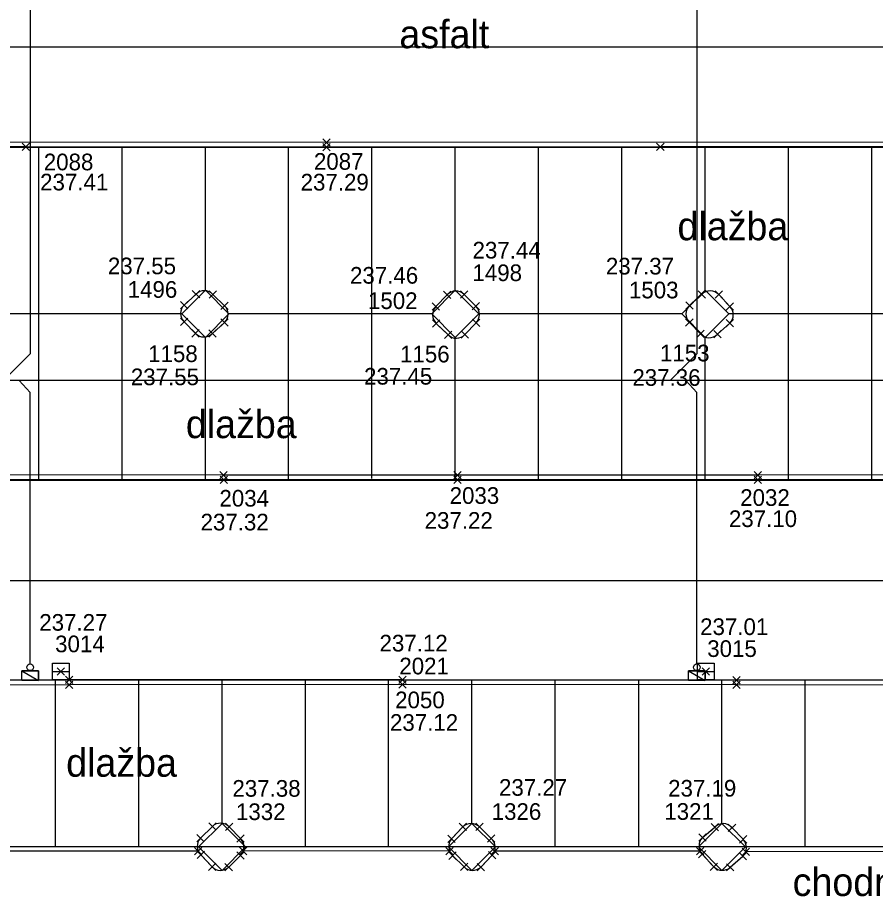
# Model space of a CAD drawing. Extents: x -264165 to -263733, y -1242319 to -1242245.
# Drawn here: x -263851.2 to -263825.46, y -1242299.47 to -1242273.09 of the extents above; entities that cross this region are included whole.
import ezdxf

# ---------------------------------------------------------------- set-up
doc = ezdxf.new("R2010")
doc.units = 0
for name, color, linetype in [('KFA_BOD_CISLO', 7, 'Continuous'), ('KFA_BOD_SYMBOL', 7, 'Continuous'), ('KFA_BOD_VYSKA', 7, 'Continuous'), ('KFA_SO_20-2_OBRUBNIKY_DOLNA_HRANA', 7, 'Continuous'), ('KFA_SO_20-2_OBRUBNIKY_HORNA_HRANA', 7, 'Continuous'), ('KFA_UV_BOD_CISLO', 7, 'Continuous'), ('KFA_UV_BOD_SYMBOL', 7, 'Continuous'), ('KFA_UV_BOD_VYSKA', 7, 'Continuous'), ('POPIS', 7, 'Continuous'), ('PROJEKT_OBRUBNIKY_KOMUNIKACIE', 7, 'Continuous'), ('PROJEKT_TDZ_VODOROVNE', 7, 'Continuous'), ('SITUACIA_DSP_2D', 7, 'Continuous'), ('ULICNA_VPUST_POKLOP', 7, 'Continuous')]:
    doc.layers.add(name, color=color, linetype=linetype)

msp = doc.modelspace()

# ---------------------------------------------------------------- linework, layer by layer
at = {"layer": 'KFA_BOD_SYMBOL'}
for p, q in [((-263842.042, -1242276.948), (-263841.821, -1242276.728)), ((-263841.821, -1242276.948), (-263842.042, -1242276.728)), ((-263851.06, -1242277.086), (-263850.839, -1242276.866)), ((-263850.839, -1242277.086), (-263851.06, -1242276.866)), ((-263842.041, -1242277.09), (-263841.82, -1242276.869)), ((-263841.82, -1242277.09), (-263842.041, -1242276.869)), ((-263832.029, -1242277.086), (-263831.807, -1242276.866)), ((-263831.807, -1242277.086), (-263832.029, -1242276.866)), ((-263845.959, -1242281.505), (-263845.737, -1242281.284)), ((-263845.737, -1242281.505), (-263845.959, -1242281.284)), ((-263845.454, -1242281.512), (-263845.232, -1242281.292)), ((-263845.232, -1242281.512), (-263845.454, -1242281.292)), ((-263838.421, -1242281.525), (-263838.199, -1242281.303)), ((-263838.199, -1242281.525), (-263838.421, -1242281.303)), ((-263837.915, -1242281.512), (-263837.693, -1242281.291)), ((-263837.693, -1242281.512), (-263837.915, -1242281.291)), ((-263830.786, -1242281.512), (-263830.565, -1242281.292)), ((-263830.565, -1242281.512), (-263830.786, -1242281.292)), ((-263830.274, -1242281.518), (-263830.053, -1242281.296)), ((-263830.053, -1242281.518), (-263830.274, -1242281.296)), ((-263846.316, -1242281.83), (-263846.095, -1242281.61)), ((-263846.095, -1242281.83), (-263846.316, -1242281.61)), ((-263845.101, -1242281.853), (-263844.879, -1242281.633)), ((-263844.879, -1242281.853), (-263845.101, -1242281.633)), ((-263838.759, -1242281.877), (-263838.538, -1242281.656)), ((-263838.538, -1242281.877), (-263838.759, -1242281.656)), ((-263837.562, -1242281.867), (-263837.34, -1242281.647)), ((-263837.34, -1242281.867), (-263837.562, -1242281.647)), ((-263831.149, -1242281.843), (-263830.928, -1242281.623)), ((-263830.928, -1242281.843), (-263831.149, -1242281.623)), ((-263829.94, -1242281.874), (-263829.719, -1242281.654)), ((-263829.719, -1242281.874), (-263829.94, -1242281.654)), ((-263846.318, -1242282.335), (-263846.096, -1242282.113)), ((-263846.096, -1242282.335), (-263846.318, -1242282.113)), ((-263845.101, -1242282.35), (-263844.879, -1242282.129)), ((-263844.879, -1242282.35), (-263845.101, -1242282.129)), ((-263838.75, -1242282.38), (-263838.529, -1242282.16)), ((-263838.529, -1242282.38), (-263838.75, -1242282.16)), ((-263837.556, -1242282.366), (-263837.334, -1242282.144)), ((-263837.334, -1242282.366), (-263837.556, -1242282.144)), ((-263831.158, -1242282.35), (-263830.937, -1242282.129)), ((-263830.937, -1242282.35), (-263831.158, -1242282.129)), ((-263829.947, -1242282.374), (-263829.726, -1242282.154)), ((-263829.726, -1242282.374), (-263829.947, -1242282.154)), ((-263845.973, -1242282.68), (-263845.752, -1242282.458)), ((-263845.752, -1242282.68), (-263845.973, -1242282.458)), ((-263845.465, -1242282.683), (-263845.244, -1242282.461)), ((-263845.244, -1242282.683), (-263845.465, -1242282.461)), ((-263838.393, -1242282.722), (-263838.171, -1242282.502)), ((-263838.171, -1242282.722), (-263838.393, -1242282.502)), ((-263837.889, -1242282.717), (-263837.668, -1242282.495)), ((-263837.668, -1242282.717), (-263837.889, -1242282.495)), ((-263830.822, -1242282.694), (-263830.601, -1242282.474)), ((-263830.601, -1242282.694), (-263830.822, -1242282.474)), ((-263830.316, -1242282.708), (-263830.095, -1242282.487)), ((-263830.095, -1242282.708), (-263830.316, -1242282.487)), ((-263845.133, -1242286.937), (-263844.911, -1242286.715)), ((-263844.911, -1242286.937), (-263845.133, -1242286.715)), ((-263838.117, -1242286.931), (-263837.896, -1242286.711)), ((-263837.896, -1242286.931), (-263838.117, -1242286.711)), ((-263829.106, -1242286.933), (-263828.884, -1242286.711)), ((-263828.884, -1242286.933), (-263829.106, -1242286.711)), ((-263845.12, -1242287.078), (-263844.899, -1242286.856)), ((-263844.899, -1242287.078), (-263845.12, -1242286.856)), ((-263838.116, -1242287.076), (-263837.894, -1242286.855)), ((-263837.894, -1242287.076), (-263838.116, -1242286.855)), ((-263829.106, -1242287.073), (-263828.885, -1242286.852)), ((-263828.885, -1242287.073), (-263829.106, -1242286.852)), ((-263839.762, -1242293.073), (-263839.541, -1242292.853)), ((-263839.541, -1242293.073), (-263839.762, -1242292.853)), ((-263849.767, -1242293.228), (-263849.546, -1242293.007)), ((-263849.546, -1242293.228), (-263849.767, -1242293.007)), ((-263849.764, -1242293.08), (-263849.542, -1242292.86)), ((-263849.542, -1242293.08), (-263849.764, -1242292.86)), ((-263839.759, -1242293.218), (-263839.538, -1242292.997)), ((-263839.538, -1242293.218), (-263839.759, -1242292.997)), ((-263829.742, -1242293.083), (-263829.521, -1242292.863)), ((-263829.521, -1242293.083), (-263829.742, -1242292.863)), ((-263829.741, -1242293.231), (-263829.519, -1242293.011)), ((-263829.519, -1242293.231), (-263829.741, -1242293.011)), ((-263845.468, -1242297.478), (-263845.247, -1242297.258)), ((-263845.247, -1242297.478), (-263845.468, -1242297.258)), ((-263844.965, -1242297.492), (-263844.743, -1242297.272)), ((-263844.743, -1242297.492), (-263844.965, -1242297.272)), ((-263837.953, -1242297.492), (-263837.731, -1242297.271)), ((-263837.731, -1242297.492), (-263837.953, -1242297.271)), ((-263837.457, -1242297.492), (-263837.236, -1242297.271)), ((-263837.236, -1242297.492), (-263837.457, -1242297.271)), ((-263830.394, -1242297.497), (-263830.174, -1242297.275)), ((-263830.174, -1242297.497), (-263830.394, -1242297.275)), ((-263829.878, -1242297.518), (-263829.656, -1242297.296)), ((-263829.656, -1242297.518), (-263829.878, -1242297.296)), ((-263830.766, -1242297.813), (-263830.545, -1242297.593)), ((-263830.545, -1242297.813), (-263830.766, -1242297.593)), ((-263845.826, -1242297.832), (-263845.605, -1242297.61)), ((-263845.605, -1242297.832), (-263845.826, -1242297.61)), ((-263844.625, -1242297.84), (-263844.404, -1242297.62)), ((-263844.404, -1242297.84), (-263844.625, -1242297.62)), ((-263838.296, -1242297.847), (-263838.074, -1242297.627)), ((-263838.074, -1242297.847), (-263838.296, -1242297.627)), ((-263837.101, -1242297.843), (-263836.879, -1242297.622)), ((-263836.879, -1242297.843), (-263837.101, -1242297.622)), ((-263829.546, -1242297.865), (-263829.325, -1242297.644)), ((-263829.325, -1242297.865), (-263829.546, -1242297.644)), ((-263845.892, -1242298.217), (-263845.671, -1242297.995)), ((-263845.671, -1242298.217), (-263845.892, -1242297.995)), ((-263845.811, -1242298.33), (-263845.59, -1242298.11)), ((-263845.59, -1242298.33), (-263845.811, -1242298.11)), ((-263844.541, -1242298.215), (-263844.319, -1242297.994)), ((-263844.319, -1242298.215), (-263844.541, -1242297.994)), ((-263838.35, -1242298.221), (-263838.128, -1242297.999)), ((-263838.128, -1242298.221), (-263838.35, -1242297.999)), ((-263837.072, -1242298.343), (-263836.851, -1242298.123)), ((-263836.851, -1242298.343), (-263837.072, -1242298.123)), ((-263836.998, -1242298.221), (-263836.777, -1242298.001)), ((-263836.777, -1242298.221), (-263836.998, -1242298.001)), ((-263830.834, -1242298.224), (-263830.612, -1242298.002)), ((-263830.612, -1242298.224), (-263830.834, -1242298.002)), ((-263830.777, -1242298.312), (-263830.556, -1242298.09)), ((-263830.556, -1242298.312), (-263830.777, -1242298.09)), ((-263829.465, -1242298.241), (-263829.244, -1242298.019)), ((-263829.244, -1242298.241), (-263829.465, -1242298.019)), ((-263844.628, -1242298.35), (-263844.407, -1242298.129)), ((-263844.407, -1242298.35), (-263844.628, -1242298.129)), ((-263838.263, -1242298.355), (-263838.041, -1242298.133)), ((-263838.041, -1242298.355), (-263838.263, -1242298.133)), ((-263829.557, -1242298.37), (-263829.335, -1242298.15)), ((-263829.335, -1242298.37), (-263829.557, -1242298.15)), ((-263845.476, -1242298.688), (-263845.254, -1242298.468)), ((-263845.254, -1242298.688), (-263845.476, -1242298.468)), ((-263844.979, -1242298.701), (-263844.758, -1242298.48)), ((-263844.758, -1242298.701), (-263844.979, -1242298.48)), ((-263837.915, -1242298.694), (-263837.693, -1242298.474)), ((-263837.693, -1242298.694), (-263837.915, -1242298.474)), ((-263837.416, -1242298.7), (-263837.194, -1242298.478)), ((-263837.194, -1242298.7), (-263837.416, -1242298.478)), ((-263830.421, -1242298.69), (-263830.2, -1242298.468)), ((-263830.2, -1242298.69), (-263830.421, -1242298.468)), ((-263829.932, -1242298.705), (-263829.71, -1242298.485)), ((-263829.71, -1242298.705), (-263829.932, -1242298.485))]:
    msp.add_line(p, q, dxfattribs=at)
at = {"layer": 'KFA_SO_20-2_OBRUBNIKY_DOLNA_HRANA'}
for points in [[(-263816.727, -1242276.824), (-263824.896, -1242276.832), (-263841.932, -1242276.838), (-263860.969, -1242276.825), (-263872.991, -1242276.822), (-263881, -1242276.818), (-263897.019, -1242276.831), (-263905.035, -1242276.846), (-263913.057, -1242276.848), (-263917.557, -1242276.899)], [(-263817.074, -1242276.98), (-263824.904, -1242276.976), (-263831.918, -1242276.976), (-263841.931, -1242276.979), (-263850.949, -1242276.976), (-263860.958, -1242276.969), (-263872.991, -1242276.965), (-263880.996, -1242276.964), (-263889.006, -1242276.968), (-263897.017, -1242276.976), (-263905.035, -1242276.99), (-263913.048, -1242276.994), (-263917.092, -1242277.009)], [(-263819.103, -1242286.786), (-263819.439, -1242286.959), (-263828.996, -1242286.962), (-263838.005, -1242286.965), (-263845.009, -1242286.967), (-263853.017, -1242286.968), (-263861.032, -1242286.966), (-263868.037, -1242286.96), (-263877.037, -1242286.952), (-263886.053, -1242286.951), (-263895.068, -1242286.953), (-263904.067, -1242286.955), (-263910.084, -1242286.961), (-263917.346, -1242286.958)], [(-263819.419, -1242286.819), (-263828.995, -1242286.822), (-263838.007, -1242286.821), (-263845.022, -1242286.826), (-263853.012, -1242286.818), (-263861.03, -1242286.825), (-263868.034, -1242286.816), (-263877.043, -1242286.812), (-263886.05, -1242286.81), (-263895.064, -1242286.807), (-263904.07, -1242286.816), (-263910.08, -1242286.821), (-263917.062, -1242286.824)], [(-263817.492, -1242292.982), (-263829.632, -1242292.973), (-263839.651, -1242292.963), (-263849.653, -1242292.97), (-263858.67, -1242292.978), (-263866.671, -1242292.969), (-263877.683, -1242292.971), (-263887.693, -1242292.984), (-263898.705, -1242293.002), (-263909.705, -1242293.003), (-263917.41, -1242292.997)], [(-263817.431, -1242293.129), (-263829.63, -1242293.121), (-263839.649, -1242293.107), (-263849.656, -1242293.117), (-263858.667, -1242293.124), (-263866.668, -1242293.115), (-263877.682, -1242293.116), (-263887.695, -1242293.128), (-263898.705, -1242293.142), (-263909.706, -1242293.151), (-263917.057, -1242293.143)]]:
    msp.add_lwpolyline(points, dxfattribs=at)
at = {"layer": 'KFA_SO_20-2_OBRUBNIKY_HORNA_HRANA'}
for p, q in [((-263845.848, -1242281.394), (-263846.205, -1242281.72)), ((-263844.99, -1242281.743), (-263845.343, -1242281.402)), ((-263838.31, -1242281.414), (-263838.649, -1242281.766)), ((-263837.451, -1242281.757), (-263837.804, -1242281.401)), ((-263830.676, -1242281.402), (-263831.039, -1242281.733)), ((-263829.829, -1242281.764), (-263830.164, -1242281.407)), ((-263846.207, -1242282.224), (-263845.862, -1242282.569)), ((-263845.355, -1242282.572), (-263844.99, -1242282.239)), ((-263838.639, -1242282.27), (-263838.282, -1242282.612)), ((-263837.779, -1242282.606), (-263837.445, -1242282.255)), ((-263830.711, -1242282.584), (-263831.047, -1242282.239)), ((-263830.205, -1242282.597), (-263829.836, -1242282.264)), ((-263845.715, -1242297.721), (-263845.357, -1242297.368)), ((-263844.854, -1242297.382), (-263844.514, -1242297.73)), ((-263837.842, -1242297.381), (-263838.185, -1242297.737)), ((-263837.346, -1242297.381), (-263836.99, -1242297.732)), ((-263830.655, -1242297.703), (-263830.284, -1242297.386)), ((-263829.767, -1242297.407), (-263829.436, -1242297.754)), ((-263845.781, -1242298.106), (-263851.901, -1242298.107)), ((-263838.239, -1242298.11), (-263844.43, -1242298.104)), ((-263830.723, -1242298.113), (-263836.888, -1242298.111)), ((-263823.183, -1242298.117), (-263829.355, -1242298.13)), ((-263845.365, -1242298.578), (-263845.7, -1242298.22)), ((-263844.518, -1242298.239), (-263844.868, -1242298.59)), ((-263837.804, -1242298.584), (-263838.152, -1242298.244)), ((-263836.961, -1242298.233), (-263837.305, -1242298.589)), ((-263830.311, -1242298.579), (-263830.666, -1242298.201)), ((-263829.821, -1242298.595), (-263829.446, -1242298.26))]:
    msp.add_line(p, q, dxfattribs=at)
for centre, major_axis, ratio, start_param, end_param in [((-263845.599, -1242281.636), (-0.343, 0.056), 0.999175, 4.045169, 5.673101), ((-263838.051, -1242281.645), (-0.126, -0.323), 0.999722, 2.721671, 4.357418), ((-263830.422, -1242281.651), (-0.309, -0.176), 0.999729, 3.379744, 4.99023), ((-263845.953, -1242281.973), (-0.018, -0.356), 0.999068, 3.974465, 5.542291), ((-263845.226, -1242281.991), (0.06, 0.337), 0.999412, 4.079854, 5.699677), ((-263838.401, -1242282.013), (-0.079, -0.341), 0.999704, 4.155248, 5.763516), ((-263837.699, -1242282.009), (-0.144, 0.323), 0.99968, 3.523747, 5.0845), ((-263830.804, -1242281.99), (-0.022, -0.347), 0.999146, 3.9461, 5.574386), ((-263830.083, -1242282.01), (-0.272, 0.227), 0.99997, 3.037553, 4.607722), ((-263845.607, -1242282.326), (0.351, -0.032), 0.998916, 3.994193, 5.600253), ((-263838.033, -1242282.364), (0.351, -0.012), 0.999101, 3.961069, 5.557532), ((-263830.452, -1242282.351), (0.321, 0.135), 0.999067, 3.476005, 5.100322), ((-263845.113, -1242297.625), (-0.327, -0.14), 0.997484, 3.491315, 5.065966), ((-263837.594, -1242297.626), (-0.297, -0.182), 0.999524, 3.371532, 4.952837), ((-263830.035, -1242297.634), (-0.35, 0.031), 0.999187, 3.933605, 5.587069), ((-263845.458, -1242297.963), (-0.098, -0.34), 0.997413, 4.239538, 5.808156), ((-263844.763, -1242297.982), (-0.038, 0.353), 0.998712, 3.796865, 5.39506), ((-263837.883, -1242297.972), (0.034, -0.382), 0.99692, 3.962445, 5.412131), ((-263837.217, -1242297.997), (0.045, 0.346), 0.998564, 4.096141, 5.7027), ((-263830.39, -1242297.958), (-0.074, 0.36), 0.998996, 0.600277, 2.089271), ((-263829.677, -1242298.002), (0.143, 0.315), 0.999689, 4.2992, 5.939539), ((-263845.111, -1242298.337), (0.35, -0.027), 0.996965, 3.976725, 5.551441), ((-263837.552, -1242298.324), (0.361, 0.033), 0.996835, 3.852792, 5.369992), ((-263830.057, -1242298.322), (0.357, -0.057), 0.99987, 4.093828, 5.585104)]:
    msp.add_ellipse(centre, major_axis=major_axis, ratio=ratio, start_param=start_param, end_param=end_param, dxfattribs=at)
at = {"layer": 'KFA_UV_BOD_SYMBOL'}
for p, q in [((-263850.011, -1242292.825), (-263849.79, -1242292.603)), ((-263849.79, -1242292.825), (-263850.011, -1242292.603)), ((-263830.663, -1242292.829), (-263830.442, -1242292.609)), ((-263830.442, -1242292.829), (-263830.663, -1242292.609))]:
    msp.add_line(p, q, dxfattribs=at)
at = {"layer": 'PROJEKT_OBRUBNIKY_KOMUNIKACIE'}
for p, q in [((-263917.08, -1242276.982), (-263817.068, -1242276.982)), ((-263819.568, -1242286.982), (-263917.08, -1242286.982)), ((-263817.19, -1242292.982), (-263917.08, -1242292.982)), ((-263815.601, -1242297.982), (-263917.08, -1242297.982))]:
    msp.add_line(p, q, dxfattribs=at)
for points in [[(-263845.568, -1242281.275), (-263844.861, -1242281.982), (-263845.568, -1242282.689), (-263846.275, -1242281.982), (-263845.568, -1242281.275)], [(-263838.068, -1242281.275), (-263837.361, -1242281.982), (-263838.068, -1242282.689), (-263838.775, -1242281.982), (-263838.068, -1242281.275)], [(-263830.568, -1242281.275), (-263829.861, -1242281.982), (-263830.568, -1242282.689), (-263831.275, -1242281.982), (-263830.568, -1242281.275)], [(-263845.068, -1242297.275), (-263844.361, -1242297.982), (-263845.068, -1242298.689), (-263845.775, -1242297.982), (-263845.068, -1242297.275)], [(-263837.568, -1242297.275), (-263836.861, -1242297.982), (-263837.568, -1242298.689), (-263838.275, -1242297.982), (-263837.568, -1242297.275)], [(-263830.068, -1242297.275), (-263829.361, -1242297.982), (-263830.068, -1242298.689), (-263830.775, -1242297.982), (-263830.068, -1242297.275)]]:
    msp.add_lwpolyline(points, dxfattribs=at)
at = {"layer": 'PROJEKT_TDZ_VODOROVNE'}
for p, q in [((-263817.068, -1242273.982), (-263917.477, -1242273.982)), ((-263850.568, -1242281.982), (-263850.568, -1242276.982)), ((-263848.068, -1242281.982), (-263848.068, -1242276.982)), ((-263845.568, -1242281.275), (-263845.568, -1242276.982)), ((-263843.068, -1242281.982), (-263843.068, -1242276.982)), ((-263840.568, -1242281.982), (-263840.568, -1242276.982)), ((-263838.068, -1242281.275), (-263838.068, -1242276.982)), ((-263835.568, -1242281.982), (-263835.568, -1242276.982)), ((-263833.068, -1242281.982), (-263833.068, -1242276.982)), ((-263830.568, -1242281.275), (-263830.568, -1242276.982)), ((-263828.068, -1242282.482), (-263828.068, -1242276.982)), ((-263825.568, -1242282.482), (-263825.568, -1242276.982)), ((-263846.275, -1242281.982), (-263852.361, -1242281.982)), ((-263850.568, -1242286.982), (-263850.568, -1242281.982)), ((-263848.068, -1242286.982), (-263848.068, -1242281.982)), ((-263838.775, -1242281.982), (-263844.861, -1242281.982)), ((-263843.068, -1242286.976), (-263843.068, -1242281.982)), ((-263840.568, -1242286.929), (-263840.568, -1242281.982)), ((-263831.275, -1242281.982), (-263837.361, -1242281.982)), ((-263835.568, -1242286.982), (-263835.568, -1242281.982)), ((-263833.068, -1242286.976), (-263833.068, -1242281.982)), ((-263823.775, -1242281.982), (-263829.861, -1242281.982)), ((-263828.068, -1242286.982), (-263828.068, -1242281.982)), ((-263825.568, -1242286.976), (-263825.568, -1242281.982)), ((-263845.568, -1242286.982), (-263845.568, -1242282.689)), ((-263838.068, -1242286.982), (-263838.068, -1242282.689)), ((-263830.568, -1242286.982), (-263830.568, -1242282.689)), ((-263819.531, -1242289.994), (-263917.477, -1242289.994)), ((-263850.068, -1242297.982), (-263850.068, -1242292.982)), ((-263847.568, -1242297.982), (-263847.568, -1242292.982)), ((-263845.068, -1242297.275), (-263845.068, -1242292.982)), ((-263842.568, -1242292.982), (-263842.568, -1242297.982)), ((-263840.068, -1242297.982), (-263840.068, -1242292.982)), ((-263837.568, -1242297.275), (-263837.568, -1242292.982)), ((-263835.068, -1242297.982), (-263835.068, -1242292.982)), ((-263832.568, -1242292.982), (-263832.568, -1242297.982)), ((-263830.068, -1242297.275), (-263830.068, -1242292.982)), ((-263827.568, -1242297.982), (-263827.568, -1242292.982))]:
    msp.add_line(p, q, dxfattribs=at)
at = {"layer": 'SITUACIA_DSP_2D'}
for p, q in [((-263850.824, -1242271.473), (-263850.824, -1242283.187)), ((-263830.824, -1242271.473), (-263830.824, -1242283.187)), ((-263850.824, -1242283.187), (-263851.619, -1242283.982)), ((-263830.824, -1242283.187), (-263831.619, -1242283.982)), ((-263817.941, -1242283.982), (-263870.324, -1242283.982)), ((-263817.941, -1242283.982), (-263870.324, -1242283.982)), ((-263850.824, -1242284.343), (-263851.149, -1242283.982)), ((-263830.824, -1242284.343), (-263831.149, -1242283.982)), ((-263850.824, -1242292.492), (-263850.824, -1242284.343)), ((-263830.824, -1242292.492), (-263830.824, -1242284.343)), ((-263851.074, -1242292.693), (-263850.574, -1242292.693)), ((-263851.074, -1242292.983), (-263851.074, -1242292.693)), ((-263851.074, -1242292.693), (-263850.574, -1242292.983)), ((-263851.074, -1242292.693), (-263850.574, -1242292.983)), ((-263850.574, -1242292.693), (-263851.074, -1242292.693)), ((-263850.574, -1242292.693), (-263850.574, -1242292.983)), ((-263850.574, -1242292.983), (-263850.574, -1242292.693)), ((-263831.074, -1242292.693), (-263830.574, -1242292.693)), ((-263831.074, -1242292.983), (-263831.074, -1242292.693)), ((-263831.074, -1242292.693), (-263830.574, -1242292.983)), ((-263831.074, -1242292.693), (-263830.574, -1242292.983)), ((-263830.574, -1242292.693), (-263831.074, -1242292.693)), ((-263830.824, -1242292.693), (-263830.824, -1242292.692)), ((-263830.574, -1242292.693), (-263830.574, -1242292.983)), ((-263830.574, -1242292.983), (-263830.574, -1242292.693)), ((-263850.574, -1242292.983), (-263851.074, -1242292.983)), ((-263830.574, -1242292.983), (-263831.074, -1242292.983)), ((-263815.601, -1242297.982), (-263917.08, -1242297.982))]:
    msp.add_line(p, q, dxfattribs=at)
for points in [[(-263845.568, -1242281.275), (-263844.861, -1242281.982), (-263845.568, -1242282.689), (-263846.275, -1242281.982)], [(-263838.068, -1242281.275), (-263837.361, -1242281.982), (-263838.068, -1242282.689), (-263838.775, -1242281.982)], [(-263830.568, -1242281.275), (-263829.861, -1242281.982), (-263830.568, -1242282.689), (-263831.275, -1242281.982)], [(-263845.068, -1242297.275), (-263844.361, -1242297.982), (-263845.068, -1242298.689), (-263845.775, -1242297.982)], [(-263837.568, -1242297.275), (-263836.861, -1242297.982), (-263837.568, -1242298.689), (-263838.275, -1242297.982)], [(-263830.068, -1242297.275), (-263829.361, -1242297.982), (-263830.068, -1242298.689), (-263830.775, -1242297.982)]]:
    msp.add_lwpolyline(points, close=True, dxfattribs=at)
for centre in [(-263850.824, -1242292.592), (-263830.824, -1242292.592)]:
    msp.add_circle(centre, 0.1, dxfattribs=at)
at = {"layer": 'ULICNA_VPUST_POKLOP'}
for p, q in [((-263849.9, -1242292.714), (-263849.9, -1242292.714)), ((-263830.552, -1242292.719), (-263830.552, -1242292.719))]:
    msp.add_line(p, q, dxfattribs=at)
for points in [[(-263850.15, -1242292.714), (-263850.15, -1242292.464), (-263849.65, -1242292.464), (-263849.65, -1242292.964), (-263850.15, -1242292.964), (-263850.15, -1242292.714), (-263849.65, -1242292.714)], [(-263830.802, -1242292.719), (-263830.802, -1242292.469), (-263830.302, -1242292.469), (-263830.302, -1242292.969), (-263830.802, -1242292.969), (-263830.802, -1242292.719), (-263830.302, -1242292.719)]]:
    msp.add_lwpolyline(points, dxfattribs=at)

# ---------------------------------------------------------------- texts
at = {"layer": 'KFA_BOD_CISLO'}
for s, p in [('2088', (-263850.414, -1242277.676)), ('2087', (-263842.31, -1242277.659)), ('1498', (-263837.554, -1242281.001)), ('1496', (-263847.898, -1242281.502)), ('1503', (-263832.859, -1242281.519)), ('1502', (-263840.688, -1242281.839)), ('1158', (-263847.284, -1242283.43)), ('1156', (-263839.726, -1242283.441)), ('1153', (-263831.928, -1242283.41)), ('2034', (-263845.145, -1242287.769)), ('2033', (-263838.238, -1242287.687)), ('2032', (-263829.521, -1242287.747)), ('2021', (-263839.748, -1242292.804)), ('2050', (-263839.873, -1242293.821)), ('1332', (-263844.648, -1242297.176)), ('1326', (-263836.977, -1242297.171)), ('1321', (-263831.798, -1242297.169))]:
    msp.add_text(s, height=0.5, dxfattribs=at).set_placement(p)
at = {"layer": 'KFA_BOD_VYSKA'}
for s, p in [('237.41', (-263850.524, -1242278.279)), ('237.29', (-263842.709, -1242278.282)), ('237.44', (-263837.551, -1242280.323)), ('237.55', (-263848.492, -1242280.796)), ('237.37', (-263833.551, -1242280.802)), ('237.46', (-263841.227, -1242281.078)), ('237.55', (-263847.803, -1242284.125)), ('237.45', (-263840.806, -1242284.108)), ('237.36', (-263832.755, -1242284.144)), ('237.32', (-263845.711, -1242288.484)), ('237.22', (-263838.989, -1242288.434)), ('237.10', (-263829.86, -1242288.382)), ('237.12', (-263840.342, -1242292.117)), ('237.12', (-263840.029, -1242294.498)), ('237.38', (-263844.755, -1242296.476)), ('237.27', (-263836.757, -1242296.447)), ('237.19', (-263831.683, -1242296.472))]:
    msp.add_text(s, height=0.5, dxfattribs=at).set_placement(p)
at = {"layer": 'KFA_UV_BOD_CISLO'}
for s, p in [('3014', (-263850.074, -1242292.14)), ('3015', (-263830.51, -1242292.281))]:
    msp.add_text(s, height=0.5, dxfattribs=at).set_placement(p)
at = {"layer": 'KFA_UV_BOD_VYSKA'}
for s, p in [('237.27', (-263850.55, -1242291.494)), ('237.01', (-263830.723, -1242291.623))]:
    msp.add_text(s, height=0.5, dxfattribs=at).set_placement(p)
at = {"layer": 'POPIS'}
for s, p in [('asfalt', (-263839.747, -1242274.011)), ('dlažba', (-263831.403, -1242279.775)), ('dlažba', (-263846.152, -1242285.714)), ('dlažba', (-263849.744, -1242295.876)), ('chodník', (-263827.947, -1242299.456))]:
    msp.add_text(s, height=0.8438, dxfattribs=at).set_placement(p)

doc.saveas('drawing.dxf')
